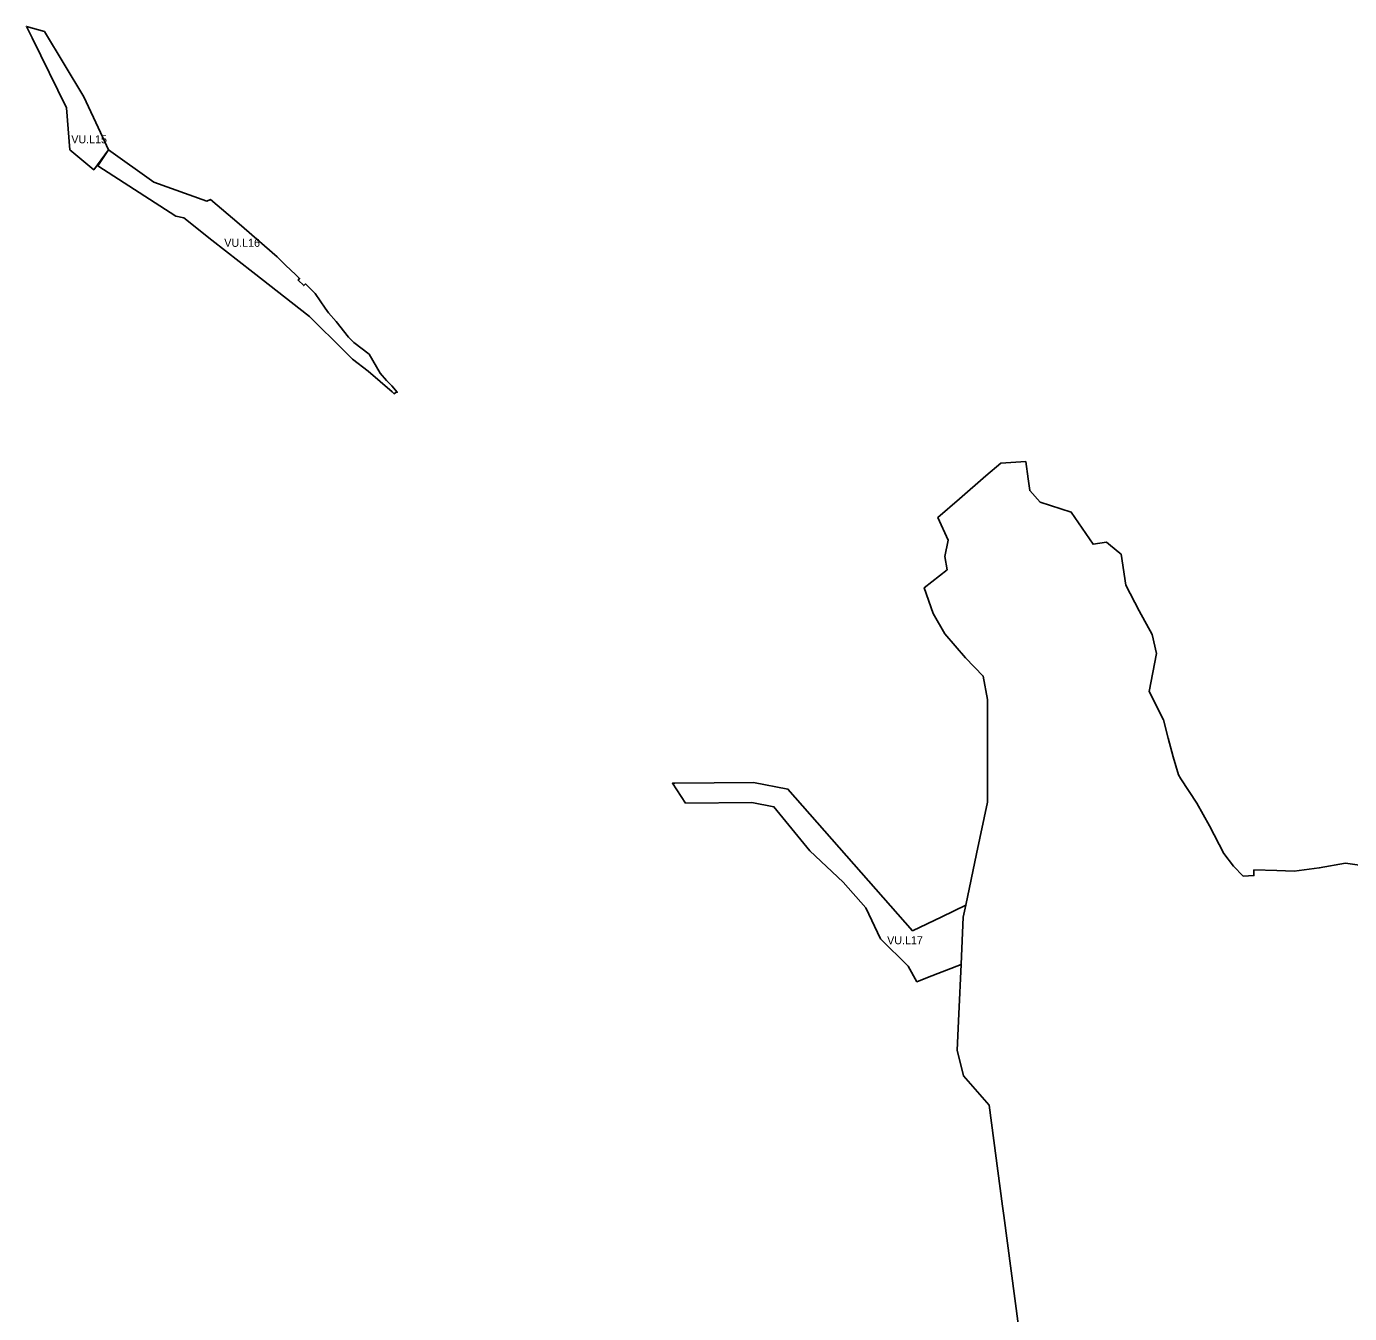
# Model space of a CAD drawing. Extents: x -439083 to -433688, y -1130252 to -1121189.
# Drawn here: x -437955 to -435972, y -1127489 to -1125559 of the extents above; entities that cross this region are included whole.
import ezdxf

# ---------------------------------------------------------------- set-up
doc = ezdxf.new("R2010")
doc.units = 0
doc.layers.add('Vrstva 28', color=7, linetype='Continuous')
doc.layers.add('Vrstva 31', color=7, linetype='Continuous')

msp = doc.modelspace()

# ---------------------------------------------------------------- linework, layer by layer
at = {"layer": 'Vrstva 28'}
for p, q in [((-437832, -1125744.4), (-437848, -1125768.5)), ((-437848, -1125768.5), (-437731.1, -1125843.9)), ((-437731.1, -1125843.9), (-437719.5, -1125846.5)), ((-436546.8, -1126876.5), (-436582.9, -1126893.9)), ((-436553.8, -1126965.3), (-436550.6, -1126894.6)), ((-436546.8, -1126876.5), (-436550.6, -1126894.6)), ((-436550.6, -1126894.6), (-436546.8, -1126876.5)), ((-436553.8, -1126965.7), (-436553.8, -1126965.3))]:
    msp.add_line(p, q, dxfattribs=at)
for points in [[(-437869.1, -1125665.1), (-437928.4, -1125566.7), (-437955.2, -1125559.4), (-437946.7, -1125576.6), (-437895, -1125681.4), (-437890.4, -1125744.1), (-437854.4, -1125774.2), (-437832, -1125744.4), (-437844.3, -1125718.1), (-437869.1, -1125665.1)], [(-437719.5, -1125846.5), (-437677.2, -1125879.7), (-437615.9, -1125927.9), (-437530.9, -1125994.2), (-437478.3, -1126046.3), (-437466.3, -1126058.1), (-437443, -1126076), (-437406.8, -1126107.3), (-437403.7, -1126110), (-437400.9, -1126107.6), (-437399.3, -1126107.8), (-437407.5, -1126097.9), (-437415.5, -1126090.2), (-437425, -1126079.1), (-437441.6, -1126050.7), (-437464.6, -1126033), (-437465.4, -1126032.3), (-437472.2, -1126024.9), (-437491, -1126001.5), (-437502.2, -1125988.6), (-437507.5, -1125981.5), (-437522.4, -1125959.9), (-437537, -1125945.2), (-437539.4, -1125947.7), (-437548.1, -1125939.5), (-437545.8, -1125937), (-437551.2, -1125931.9), (-437566.9, -1125917.1), (-437578.9, -1125905), (-437579.3, -1125904.5), (-437629, -1125861.6), (-437636.5, -1125855.2), (-437679.1, -1125818.8), (-437684.8, -1125821.2), (-437764.2, -1125792.8), (-437832, -1125744.4)], [(-435928.9, -1126820.8), (-435977.5, -1126813.8), (-436017, -1126820.8), (-436054.4, -1126825.8), (-436080.3, -1126824.9), (-436115, -1126823.7), (-436115, -1126832.2), (-436130.8, -1126833.2), (-436145.6, -1126818), (-436160.1, -1126799.2), (-436181.4, -1126757.8), (-436200.3, -1126723.8), (-436224.3, -1126687), (-436228, -1126681.3), (-436236.2, -1126654.1), (-436243.4, -1126626.5), (-436250.6, -1126599), (-436271.9, -1126556.4), (-436261.1, -1126499.5), (-436267.4, -1126470.7), (-436286.8, -1126435.6), (-436306.7, -1126397), (-436314.1, -1126350.5), (-436318.4, -1126347), (-436336.1, -1126332.4), (-436356, -1126335.5), (-436388.8, -1126287.5), (-436435.5, -1126272.6), (-436451.1, -1126255.2), (-436453.5, -1126237.3), (-436457, -1126211.7), (-436494.3, -1126213.8), (-436516.6, -1126233), (-436556.2, -1126267.3), (-436588.8, -1126295.6), (-436573.3, -1126329.4), (-436578.1, -1126353.9), (-436574.9, -1126373.9), (-436609.5, -1126401.1), (-436595.9, -1126439.4), (-436578.2, -1126469.7), (-436547.2, -1126505.7), (-436520.8, -1126533.3), (-436514.3, -1126568.1), (-436514.3, -1126687), (-436514.3, -1126722.3), (-436530.7, -1126799.9), (-436546.8, -1126876.5)], [(-436582.9, -1126893.9), (-436626.7, -1126915), (-436813.6, -1126702.6), (-436865.2, -1126692.6), (-436983.3, -1126693.7), (-436986.7, -1126693.8), (-436967.1, -1126723.6), (-436867.9, -1126722.7), (-436834.6, -1126729.1), (-436780.9, -1126795.2), (-436730.7, -1126842.3), (-436696.9, -1126880.7), (-436675, -1126927.2), (-436633.4, -1126968.2), (-436620.1, -1126991.5), (-436604.4, -1126985.3), (-436553.8, -1126965.7)], [(-436550.6, -1126894.6), (-436553.8, -1126965.3), (-436553.8, -1126965.7), (-436557.2, -1127039.4)], [(-436557.2, -1127039.4), (-436559.7, -1127094.2), (-436550.5, -1127132.4), (-436511.6, -1127176.5), (-436491.6, -1127327.6), (-436489.7, -1127342), (-436467.8, -1127507.6), (-436458.8, -1127576.8), (-436369.4, -1127691.4), (-436329.7, -1127657.1)]]:
    msp.add_lwpolyline(points, dxfattribs=at)

# ---------------------------------------------------------------- texts
at = {"layer": 'Vrstva 31'}
for s, p in [('VU.L15', (-437888, -1125734.5)), ('VU.L16', (-437658.6, -1125889.7)), ('VU.L17', (-436664.8, -1126935.2))]:
    msp.add_text(s, height=12, dxfattribs=at).set_placement(p)

doc.saveas('drawing.dxf')
